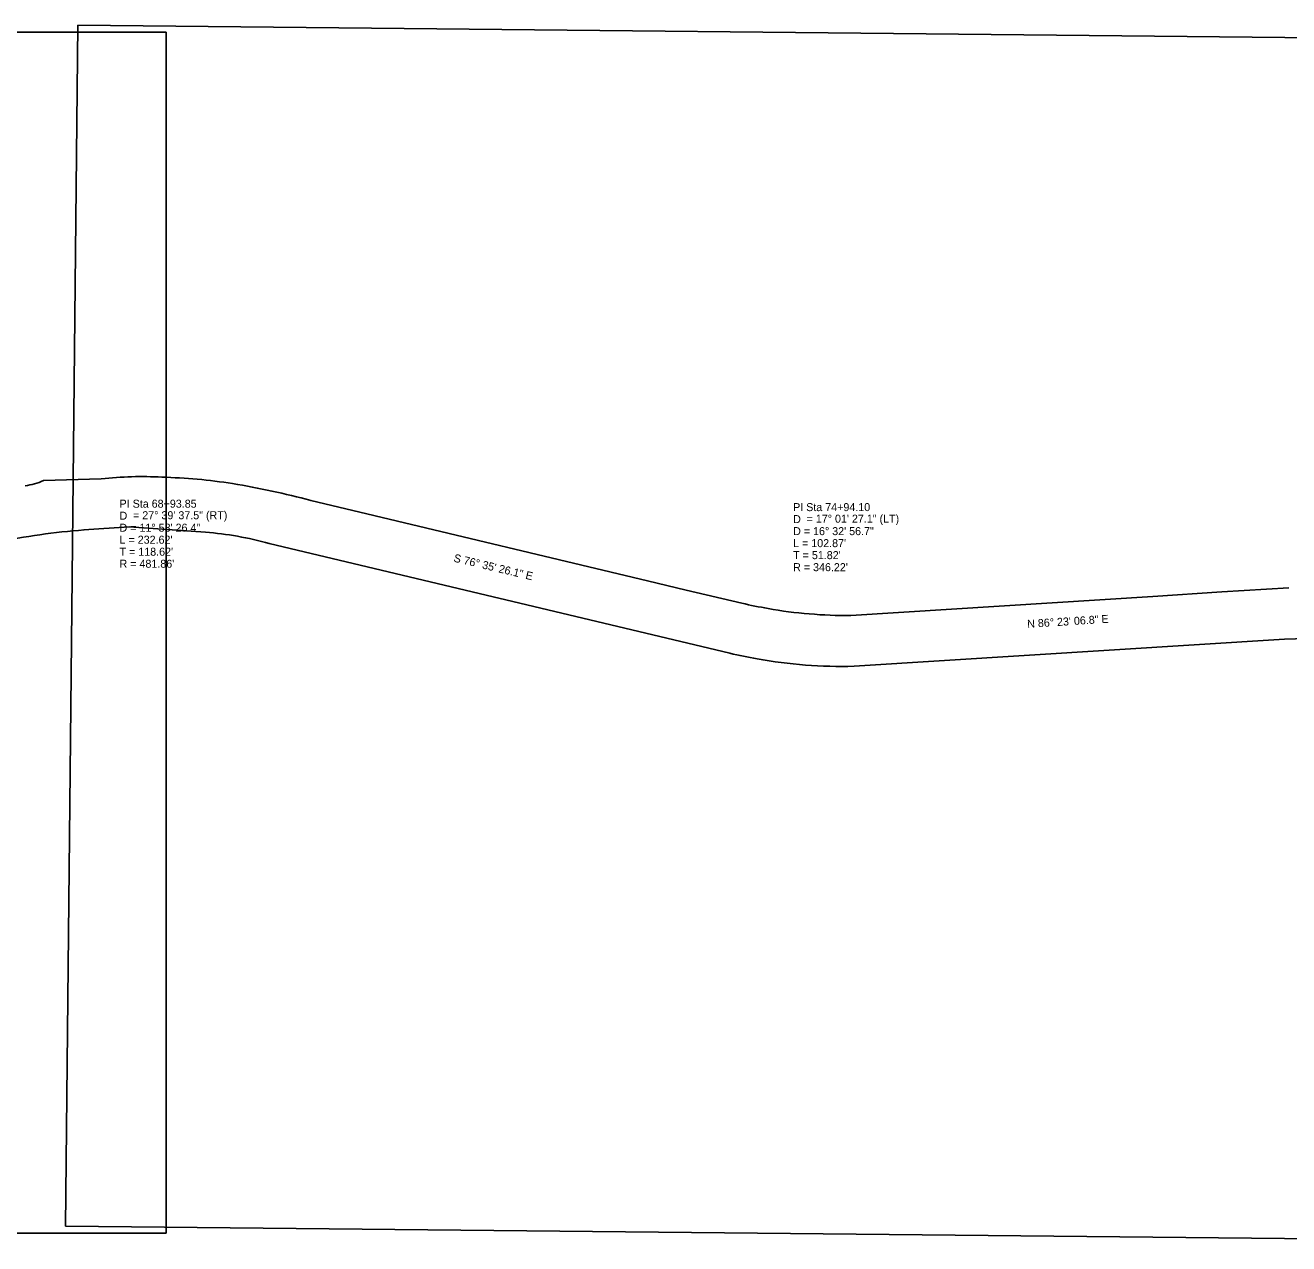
# Model space of a CAD drawing. Extents: x 925297 to 940193, y 663541 to 689899.
# Drawn here: x 933097 to 934201, y 684198 to 685264 of the extents above; entities that cross this region are included whole.
import ezdxf

# ---------------------------------------------------------------- set-up
doc = ezdxf.new("R2010")
doc.units = 0
for name, color, linetype in [('Default', 7, 'Continuous'), ('Exist Horizontal Alignment Curve and Spiral Data', 7, 'Continuous'), ('Exist Horizontal Alignment Direction Label', 7, 'Continuous'), ('Prop Shade Light', 7, 'Continuous')]:
    doc.layers.add(name, color=color, linetype=linetype)

msp = doc.modelspace()

# ---------------------------------------------------------------- linework, layer by layer
at = {"layer": 'Default'}
for p, q in [((933131.8, 684213.8), (933142.5, 685263.8)), ((933142.5, 685263.8), (934642.5, 685248.4)), ((933219.8, 685257.7), (931719.8, 685257.7)), ((933219.8, 684207.7), (933219.8, 685257.7)), ((934631.7, 684198.5), (933131.8, 684213.8)), ((931719.8, 684207.7), (933219.8, 684207.7))]:
    msp.add_line(p, q, dxfattribs=at)
at = {"layer": 'Prop Shade Light'}
for p, q in [((933112.4, 684865.7), (933163, 684867.2)), ((933346.3, 684848.3), (933389.1, 684838.1)), ((933389.1, 684838.1), (933640.7, 684778.1)), ((933187.4, 684825.2), (933147.9, 684822.6)), ((933254.2, 684820.7), (933187.4, 684825.2)), ((933712.8, 684714.7), (933309.9, 684810.7)), ((933640.7, 684778.1), (933674.5, 684770)), ((933674.5, 684770), (933723.2, 684758.4)), ((933818.5, 684747.8), (934082.6, 684764.5)), ((934082.6, 684764.5), (934143, 684768.3)), ((934143, 684768.3), (934201.4, 684772)), ((934197.8, 684727.1), (933821.3, 684703.3)), ((934237.7, 684728.2), (934197.8, 684727.1))]:
    msp.add_line(p, q, dxfattribs=at)
for centre, radius, start, end in [((933088.7, 684918.2), 57.6, 277.8498, 294.3272), ((933198.2, 684552.5), 316.7, 86.7685, 96.3695), ((933205.1, 684409.8), 459, 80.8872, 88.6344), ((933152.5, 684114.8), 758.7, 75.194, 80.4929), ((933191.1, 684236.8), 587.3, 94.216, 101.7942), ((933231.3, 684531.8), 289.7, 74.2571, 85.48), ((933798, 685072.3), 322.6, 256.5906, 260.7438), ((933816.4, 685160), 412.3, 260.1804, 270.2899), ((933798, 685072.3), 367.6, 256.5906, 260.3765), ((933809.8, 685108.5), 405.3, 259.5863, 271.6263)]:
    msp.add_arc(centre, radius, start, end, dxfattribs=at)

# ---------------------------------------------------------------- texts
at = {"layer": 'Exist Horizontal Alignment Curve and Spiral Data'}
for s, p in [('PI Sta 68+93.85', (933179, 684842)), ('PI Sta 74+94.10', (933768, 684839)), ('D', (933179, 684831.5)), ('= 27%%d 39\' 37.5" (RT)', (933190.8, 684831.9)), ('D', (933768, 684828.5)), ('= 17%%d 01\' 27.1" (LT)', (933779.8, 684828.9)), ('D = 11%%d 53\' 26.4"', (933179, 684821)), ('D = 16%%d 32\' 56.7"', (933768, 684818)), ("T = 118.62'", (933179, 684800)), ("L = 232.62'", (933179, 684810.5)), ("L = 102.87'", (933768, 684807.5)), ("R = 481.86'", (933179, 684789.5)), ("T = 51.82'", (933768, 684797)), ("R = 346.22'", (933768, 684786.5))]:
    msp.add_text(s, height=7, dxfattribs=at).set_placement(p)
at = {"layer": 'Exist Horizontal Alignment Direction Label'}
for s, rotation, p in [('S 76%%d 35\' 26.1" E', 346.5906, (933470.7, 684794.9)), ('N 86%%d 23\' 06.8" E', 3.6148, (933972.9, 684736.9))]:
    msp.add_text(s, height=7, rotation=rotation, dxfattribs=at).set_placement(p)

doc.saveas('drawing.dxf')
